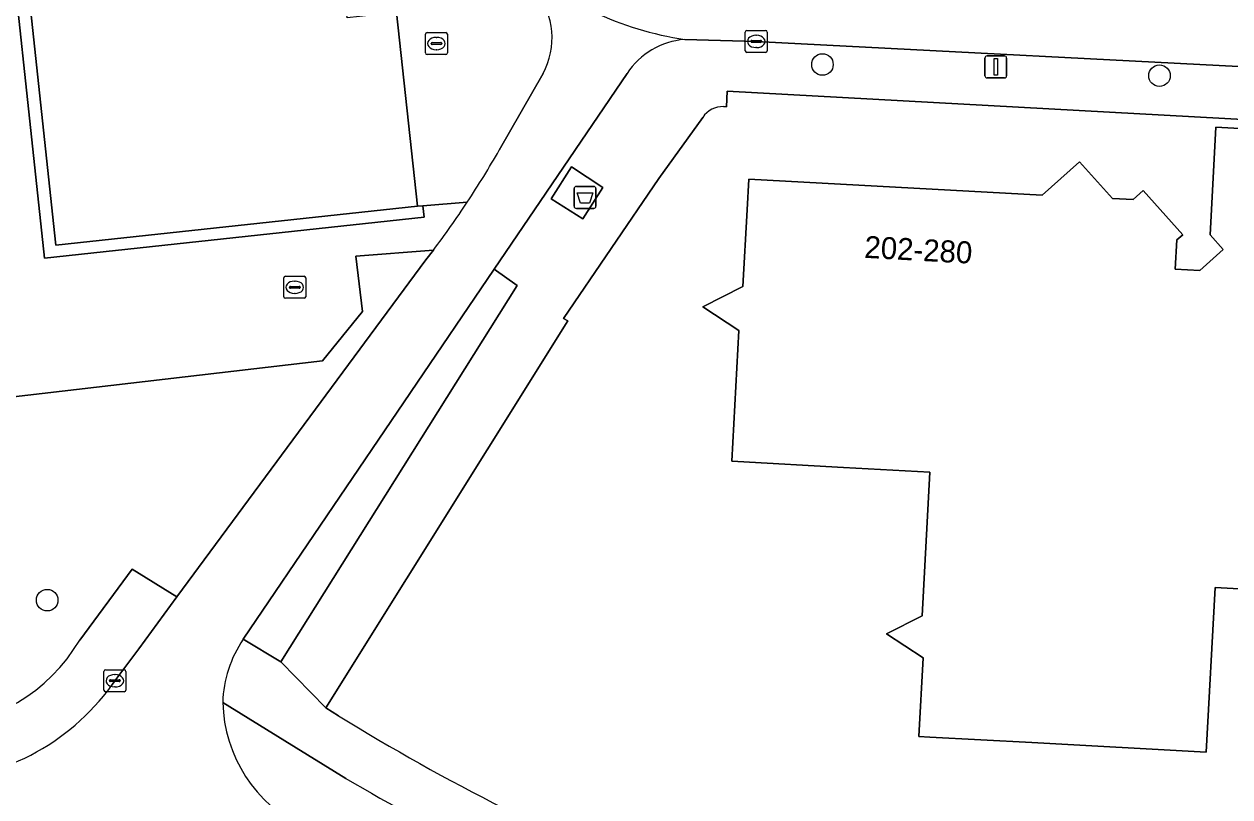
# Model space of a CAD drawing. Extents: x 161248 to 161848, y 384871 to 385383.
# Drawn here: x 161334.5 to 161389.3, y 384914.2 to 384949.3 of the extents above; entities that cross this region are included whole.
import ezdxf

# ---------------------------------------------------------------- set-up
doc = ezdxf.new("R2010")
doc.units = 0
for name, color, linetype in [('IMGEO_Afval_apart_plaats', 7, 'Continuous'), ('IMGEO_Berm_groen', 7, 'Continuous'), ('IMGEO_Boom', 7, 'Continuous'), ('IMGEO_Brandkraan', 7, 'Continuous'), ('IMGEO_Erf', 7, 'Continuous'), ('IMGEO_Fietspad_gesloten', 7, 'Continuous'), ('IMGEO_Groenvoorziening', 7, 'Continuous'), ('IMGEO_Haag', 7, 'Continuous'), ('IMGEO_Kolk', 7, 'Continuous'), ('IMGEO_Lichtmast', 7, 'Continuous'), ('IMGEO_Pand', 7, 'Continuous'), ('IMGEO_Pand_nummerreeks', 7, 'Continuous'), ('IMGEO_Rijbaan_lokaal_open', 7, 'Continuous'), ('IMGEO_Voetpad_gesloten', 7, 'Continuous'), ('IMGEO_Voetpad_open', 7, 'Continuous')]:
    doc.layers.add(name, color=color, linetype=linetype)

msp = doc.modelspace()

# ---------------------------------------------------------------- linework, layer by layer
at = {"layer": 'IMGEO_Afval_apart_plaats'}
for p, q in [((161359.468, 384941.031), (161359.468, 384941.831)), ((161359.468, 384941.831), (161359.468, 384941.031)), ((161359.568, 384941.931), (161360.358, 384941.931)), ((161360.358, 384941.931), (161359.568, 384941.931)), ((161360.458, 384941.831), (161360.458, 384941.031)), ((161360.458, 384941.031), (161360.458, 384941.831)), ((161360.358, 384940.931), (161359.568, 384940.931)), ((161359.568, 384940.931), (161360.358, 384940.931))]:
    msp.add_line(p, q, dxfattribs=at)
msp.add_lwpolyline([(161359.611, 384941.645), (161360.315, 384941.645), (161360.166, 384941.175), (161359.76, 384941.175), (161359.611, 384941.645)], dxfattribs=at)
for centre, start, end in [((161359.568, 384941.831), 90, 180), ((161359.568, 384941.831), 90, 180), ((161360.358, 384941.831), 0, 90), ((161360.358, 384941.831), 360, 90), ((161359.568, 384941.031), 180, 270), ((161359.568, 384941.031), 180, 270), ((161360.358, 384941.031), 270, 0), ((161360.358, 384941.031), 270, 0)]:
    msp.add_arc(centre, 0.1, start, end, dxfattribs=at)
at = {"layer": 'IMGEO_Berm_groen'}
msp.add_lwpolyline([(161349.092, 384915.021), (161346.317, 384916.731), (161343.493, 384918.478)], dxfattribs=at)
for centre, radius, start, end in [((161350.031, 384918.66), 6.541, 181.5976, 244.0484), ((161403.381, 385007.754), 107.456, 239.65384, 243.46089)]:
    msp.add_arc(centre, radius, start, end, dxfattribs=at)
at = {"layer": 'IMGEO_Boom'}
for centre in [(161370.755, 384947.473), (161386.077, 384946.965), (161335.512, 384923.126)]:
    msp.add_circle(centre, 0.489, dxfattribs=at)
at = {"layer": 'IMGEO_Brandkraan'}
for p, q in [((161352.707, 384948), (161352.707, 384948.852)), ((161352.782, 384948.926), (161353.634, 384948.926)), ((161352.966, 384948.42), (161352.966, 384948.432)), ((161353.009, 384948.469), (161353.407, 384948.469)), ((161353.195, 384948.706), (161353.22, 384948.706)), ((161353.45, 384948.432), (161353.45, 384948.42)), ((161353.708, 384948.852), (161353.708, 384948)), ((161353.634, 384947.926), (161352.782, 384947.926)), ((161353.404, 384948.383), (161353.006, 384948.383)), ((161353.218, 384948.146), (161353.193, 384948.146))]:
    msp.add_line(p, q, dxfattribs=at)
for points in [[(161352.707, 384948), (161352.707, 384948.852)], [(161352.782, 384948.926), (161353.634, 384948.926)], [(161353.708, 384948.852), (161353.708, 384948)], [(161353.634, 384947.926), (161352.782, 384947.926)]]:
    msp.add_lwpolyline(points, dxfattribs=at)
for centre, radius, start, end in [((161352.784, 384948.85), 0.0765, 91.552, 178.448), ((161352.784, 384948.85), 0.0765, 91.552, 178.448), ((161353.006, 384948.429), 0.0403, 85.8775, 175.7526), ((161353.003, 384948.419), 0.0366, 178.938, 274.7102), ((161353.407, 384948.426), 0.043, 264.8664, 352.4533), ((161353.411, 384948.431), 0.0386, 1.7309, 96.639), ((161353.632, 384948.85), 0.0765, 1.552, 88.448), ((161353.632, 384948.85), 0.0765, 1.552, 88.448), ((161352.784, 384948.002), 0.0765, 181.552, 268.448), ((161352.784, 384948.002), 0.0765, 181.552, 268.448), ((161353.632, 384948.002), 0.0765, 271.552, 358.448), ((161353.632, 384948.002), 0.0765, 271.552, 358.448)]:
    msp.add_arc(centre, radius, start, end, dxfattribs=at)
for centre, major_axis, ratio, start_param, end_param in [((161353.194, 384948.426), (-0.387, 0.002), 0.722429, 4.712389, 7.853982), ((161353.219, 384948.426), (-0.39, 0.002), 0.717154, 1.570796, 4.712389)]:
    msp.add_ellipse(centre, major_axis=major_axis, ratio=ratio, start_param=start_param, end_param=end_param, dxfattribs=at)
at = {"layer": 'IMGEO_Erf'}
for points in [[(161437.515, 384942.215), (161436.725, 384942.209), (161437.252, 384941.619), (161436.953, 384936.313), (161431.959, 384936.555), (161408.657, 384937.683), (161408.674, 384937.993), (161408.956, 384942.985), (161409.594, 384943.555), (161403.643, 384943.814), (161403.665, 384944.222), (161366.425, 384946.266), (161366.386, 384945.555), (161366.264, 384945.56)], [(161365.315, 384945.065), (161363.318, 384942.295), (161358.986, 384935.923), (161359.186, 384935.82), (161348.18, 384918.225), (161348.748, 384917.875)], [(161396.201, 384923.284), (161388.608, 384923.701), (161388.197, 384916.214), (161380.273, 384916.649), (161375.632, 384916.903), (161375.143, 384916.93), (161375.339, 384920.503), (161373.674, 384921.59), (161375.285, 384922.406), (161375.643, 384928.944), (161371.706, 384929.16), (161366.914, 384929.424), (161366.635, 384929.439), (161366.961, 384935.385), (161365.323, 384936.455), (161367.143, 384937.376), (161367.335, 384940.872), (161367.411, 384942.26), (161380.747, 384941.528), (161382.446, 384943.051), (161383.943, 384941.381), (161384.876, 384941.33), (161385.335, 384941.741), (161387.131, 384939.737), (161386.87, 384939.503), (161386.796, 384938.172), (161387.909, 384938.111), (161388.975, 384939.066), (161388.374, 384939.738), (161388.626, 384944.334), (161388.642, 384944.623), (161402.4, 384943.868)]]:
    msp.add_lwpolyline(points, dxfattribs=at)
for centre, radius, start, end in [((161366.217, 384944.493), 1.068, 87.4663, 147.6269), ((161402.791, 385005.617), 103.05, 238.37002, 247.93312)]:
    msp.add_arc(centre, radius, start, end, dxfattribs=at)
at = {"layer": 'IMGEO_Fietspad_gesloten'}
for points in [[(161344.427, 384921.346), (161355.831, 384938.171), (161361.875, 384947.059)], [(161358.055, 384947.061), (161356.066, 384943.583)], [(161353.067, 384939.032), (161352.732, 384938.592), (161341.413, 384923.282), (161339.671, 384920.911), (161338.589, 384919.464), (161338.457, 384919.26)]]:
    msp.add_lwpolyline(points, dxfattribs=at)
for centre, radius, start, end in [((161366.86, 384963.899), 15.474, 228.8729, 261.1978), ((161355.084, 384948.673), 3.38, 331.5226, 38.9105), ((161364.731, 384945.217), 3.399, 94.0321, 147.178), ((161318.363, 384965.194), 43.457, 326.5147, 330.1784), ((161318.717, 384964.883), 42.99, 323.0359, 326.601), ((161348.794, 384918.338), 5.302, 145.4371, 178.4859), ((161329.83, 384925.556), 10.68, 271.125, 323.8791), ((161350.031, 384918.66), 6.541, 181.5976, 244.0484)]:
    msp.add_arc(centre, radius, start, end, dxfattribs=at)
at = {"layer": 'IMGEO_Groenvoorziening'}
msp.add_lwpolyline([(161336.989, 384921.31), (161339.374, 384924.535), (161341.413, 384923.282), (161352.732, 384938.592), (161353.067, 384939.032), (161349.538, 384938.768), (161349.844, 384936.245), (161348.022, 384934.003), (161333.73, 384932.332), (161329.539, 384937.213), (161322.803, 385000)], dxfattribs=at)
msp.add_lwpolyline([(161355.831, 384938.171), (161344.427, 384921.346), (161346.132, 384920.317), (161356.875, 384937.434)], close=True, dxfattribs=at)
msp.add_arc((161330.018, 384925.42), 8.092, 272.132, 329.4792, dxfattribs=at)
at = {"layer": 'IMGEO_Haag'}
msp.add_lwpolyline([(161355.831, 384938.171), (161344.427, 384921.346), (161346.132, 384920.317), (161356.875, 384937.434)], close=True, dxfattribs=at)
at = {"layer": 'IMGEO_Kolk'}
for p, q in [((161367.245, 384948.098), (161367.245, 384948.95)), ((161367.32, 384949.024), (161368.172, 384949.024)), ((161368.246, 384948.95), (161368.246, 384948.098)), ((161367.504, 384948.518), (161367.504, 384948.53)), ((161367.942, 384948.481), (161367.544, 384948.481)), ((161367.547, 384948.567), (161367.945, 384948.567)), ((161367.733, 384948.804), (161367.758, 384948.804)), ((161367.988, 384948.53), (161367.988, 384948.518)), ((161368.172, 384948.024), (161367.32, 384948.024)), ((161367.756, 384948.244), (161367.731, 384948.244)), ((161346.267, 384936.92), (161346.267, 384937.772)), ((161346.342, 384937.846), (161347.194, 384937.846)), ((161346.755, 384937.626), (161346.78, 384937.626)), ((161347.268, 384937.772), (161347.268, 384936.92)), ((161346.526, 384937.34), (161346.526, 384937.352)), ((161346.964, 384937.303), (161346.566, 384937.303)), ((161346.569, 384937.389), (161346.967, 384937.389)), ((161346.778, 384937.066), (161346.753, 384937.066)), ((161347.01, 384937.352), (161347.01, 384937.34)), ((161347.194, 384936.846), (161346.342, 384936.846)), ((161338.088, 384919.038), (161338.088, 384919.89)), ((161338.163, 384919.964), (161339.015, 384919.964)), ((161339.089, 384919.89), (161339.089, 384919.038)), ((161338.347, 384919.458), (161338.347, 384919.47)), ((161338.785, 384919.421), (161338.387, 384919.421)), ((161338.39, 384919.507), (161338.788, 384919.507)), ((161338.576, 384919.744), (161338.601, 384919.744)), ((161338.831, 384919.47), (161338.831, 384919.458)), ((161339.015, 384918.964), (161338.163, 384918.964)), ((161338.599, 384919.184), (161338.574, 384919.184))]:
    msp.add_line(p, q, dxfattribs=at)
for points in [[(161367.245, 384948.098), (161367.245, 384948.95)], [(161367.32, 384949.024), (161368.172, 384949.024)], [(161368.246, 384948.95), (161368.246, 384948.098)], [(161368.172, 384948.024), (161367.32, 384948.024)], [(161346.267, 384936.92), (161346.267, 384937.772)], [(161346.342, 384937.846), (161347.194, 384937.846)], [(161347.268, 384937.772), (161347.268, 384936.92)], [(161347.194, 384936.846), (161346.342, 384936.846)], [(161338.088, 384919.038), (161338.088, 384919.89)], [(161338.163, 384919.964), (161339.015, 384919.964)], [(161339.089, 384919.89), (161339.089, 384919.038)], [(161339.015, 384918.964), (161338.163, 384918.964)]]:
    msp.add_lwpolyline(points, dxfattribs=at)
for centre, radius, start, end in [((161367.322, 384948.948), 0.0765, 91.552, 178.448), ((161367.322, 384948.948), 0.0765, 91.552, 178.448), ((161368.17, 384948.948), 0.0765, 1.552, 88.448), ((161368.17, 384948.948), 0.0765, 1.552, 88.448), ((161367.544, 384948.527), 0.0403, 85.8775, 175.7526), ((161367.541, 384948.517), 0.0366, 178.938, 274.7102), ((161367.945, 384948.524), 0.043, 264.8664, 352.4533), ((161367.949, 384948.529), 0.0386, 1.7309, 96.639), ((161367.322, 384948.1), 0.0765, 181.552, 268.448), ((161367.322, 384948.1), 0.0765, 181.552, 268.448), ((161368.17, 384948.1), 0.0765, 271.552, 358.448), ((161368.17, 384948.1), 0.0765, 271.552, 358.448), ((161346.344, 384937.77), 0.0765, 91.552, 178.448), ((161346.344, 384937.77), 0.0765, 91.552, 178.448), ((161347.192, 384937.77), 0.0765, 1.552, 88.448), ((161347.192, 384937.77), 0.0765, 1.552, 88.448), ((161346.344, 384936.922), 0.0765, 181.552, 268.448), ((161346.344, 384936.922), 0.0765, 181.552, 268.448), ((161346.566, 384937.349), 0.0403, 85.8775, 175.7526), ((161346.563, 384937.339), 0.0366, 178.938, 274.7102), ((161346.967, 384937.346), 0.043, 264.8664, 352.4533), ((161346.971, 384937.351), 0.0386, 1.7309, 96.639), ((161347.192, 384936.922), 0.0765, 271.552, 358.448), ((161347.192, 384936.922), 0.0765, 271.552, 358.448), ((161338.165, 384919.888), 0.0765, 91.552, 178.448), ((161338.165, 384919.888), 0.0765, 91.552, 178.448), ((161339.013, 384919.888), 0.0765, 1.552, 88.448), ((161339.013, 384919.888), 0.0765, 1.552, 88.448), ((161338.387, 384919.467), 0.0403, 85.8775, 175.7526), ((161338.384, 384919.457), 0.0366, 178.938, 274.7102), ((161338.788, 384919.464), 0.043, 264.8664, 352.4533), ((161338.792, 384919.469), 0.0386, 1.7309, 96.639), ((161338.165, 384919.04), 0.0765, 181.552, 268.448), ((161338.165, 384919.04), 0.0765, 181.552, 268.448), ((161339.013, 384919.04), 0.0765, 271.552, 358.448), ((161339.013, 384919.04), 0.0765, 271.552, 358.448)]:
    msp.add_arc(centre, radius, start, end, dxfattribs=at)
for centre, major_axis, ratio, start_param, end_param in [((161367.732, 384948.524), (-0.387, 0.002), 0.722429, 4.712389, 7.853982), ((161367.757, 384948.524), (-0.39, 0.002), 0.717154, 1.570796, 4.712389), ((161346.754, 384937.346), (-0.387, 0.002), 0.722429, 4.712389, 7.853982), ((161346.779, 384937.346), (-0.39, 0.002), 0.717154, 1.570796, 4.712389), ((161338.575, 384919.464), (-0.387, 0.002), 0.722429, 4.712389, 7.853982), ((161338.6, 384919.464), (-0.39, 0.002), 0.717154, 1.570796, 4.712389)]:
    msp.add_ellipse(centre, major_axis=major_axis, ratio=ratio, start_param=start_param, end_param=end_param, dxfattribs=at)
at = {"layer": 'IMGEO_Lichtmast'}
for p, q in [((161378.239, 384947.865), (161379.029, 384947.865)), ((161379.029, 384947.865), (161378.239, 384947.865)), ((161378.139, 384946.965), (161378.139, 384947.765)), ((161378.139, 384947.765), (161378.139, 384946.965)), ((161379.129, 384947.765), (161379.129, 384946.965)), ((161379.129, 384946.965), (161379.129, 384947.765)), ((161379.029, 384946.865), (161378.239, 384946.865)), ((161378.239, 384946.865), (161379.029, 384946.865))]:
    msp.add_line(p, q, dxfattribs=at)
msp.add_lwpolyline([(161378.559, 384947.74), (161378.709, 384947.74), (161378.709, 384946.99), (161378.559, 384946.99), (161378.559, 384947.74)], dxfattribs=at)
for centre, start, end in [((161378.239, 384947.765), 90, 180), ((161378.239, 384947.765), 90, 180), ((161379.029, 384947.765), 0, 90), ((161379.029, 384947.765), 360, 90), ((161378.239, 384946.965), 180, 270), ((161378.239, 384946.965), 180, 270), ((161379.029, 384946.965), 270, 0), ((161379.029, 384946.965), 270, 0)]:
    msp.add_arc(centre, 0.1, start, end, dxfattribs=at)
at = {"layer": 'IMGEO_Pand'}
msp.add_lwpolyline([(161349.099, 384971.364), (161346.806, 384971.118), (161346.282, 384975.989), (161347.495, 384976.119), (161347.464, 384976.414), (161332.09, 384974.761), (161335.907, 384939.267), (161352.34, 384941.034), (161351.394, 384949.836), (161349.145, 384949.594), (161348.631, 384954.373), (161349.881, 384954.507), (161349.815, 384955.119), (161348.591, 384954.987), (161348.072, 384959.82), (161348.677, 384959.885), (161348.309, 384963.303), (161347.699, 384963.238), (161346.913, 384970.539), (161349.162, 384970.781)], close=True, dxfattribs=at)
msp.add_lwpolyline([(161402.4, 384943.868), (161388.642, 384944.623), (161388.626, 384944.334), (161388.374, 384939.738), (161388.975, 384939.066), (161387.909, 384938.111), (161386.796, 384938.172), (161386.87, 384939.503), (161387.131, 384939.737), (161385.335, 384941.741), (161384.876, 384941.33), (161383.943, 384941.381), (161382.446, 384943.051), (161380.747, 384941.528), (161367.411, 384942.26), (161367.335, 384940.872), (161367.143, 384937.376), (161365.323, 384936.455), (161366.961, 384935.385), (161366.635, 384929.439), (161366.914, 384929.424), (161371.706, 384929.16), (161375.643, 384928.944), (161375.285, 384922.406), (161373.674, 384921.59), (161375.339, 384920.503), (161375.143, 384916.93), (161375.632, 384916.903), (161380.273, 384916.649), (161388.197, 384916.214), (161388.608, 384923.701), (161396.201, 384923.284)], dxfattribs=at)
at = {"layer": 'IMGEO_Rijbaan_lokaal_open'}
for points in [[(161326.219, 385023.721), (161335.826, 385024.754), (161335.778, 385025.258), (161326.818, 385024.285), (161326.594, 385026.253), (161319.802, 385024.058), (161320.382, 385022.568), (161322.803, 385000), (161329.539, 384937.213), (161333.73, 384932.332), (161348.022, 384934.003), (161349.844, 384936.245), (161349.538, 384938.768), (161353.067, 384939.032)], [(161354.608, 384941.218), (161352.588, 384941.054), (161352.645, 384940.528), (161335.385, 384938.672), (161333.36, 384957.504), (161332.965, 384957.461), (161331.628, 384969.898), (161332.002, 384969.938), (161331.017, 384979.097), (161330.667, 384979.059), (161329.341, 384991.388), (161329.661, 384991.422), (161328.734, 385000), (161328.683, 385000.47), (161328.371, 385000.44), (161327.034, 385012.879), (161327.381, 385012.916), (161326.219, 385023.721)], [(161364.492, 384948.607), (161367.746, 384948.524), (161392.878, 384947.213), (161402.342, 384946.764), (161409.808, 384946.409), (161436.678, 384945.133)]]:
    msp.add_lwpolyline(points, dxfattribs=at)
for centre, radius, start, end in [((161366.86, 384963.899), 15.474, 228.8729, 261.1978), ((161318.717, 384964.883), 42.99, 323.0359, 326.601)]:
    msp.add_arc(centre, radius, start, end, dxfattribs=at)
at = {"layer": 'IMGEO_Voetpad_gesloten'}
msp.add_lwpolyline([(161359.352, 384942.829), (161358.427, 384941.375), (161359.865, 384940.463), (161360.772, 384941.881)], close=True, dxfattribs=at)
at = {"layer": 'IMGEO_Voetpad_open'}
for points in [[(161343.203, 385026.481), (161343.3, 385025.559), (161343.862, 385025.619), (161345.069, 385014.386), (161345.626, 385014.446), (161346.272, 385008.441), (161345.12, 385008.375), (161345.635, 385003.548), (161346.825, 384992.221), (161347.327, 384987.554), (161347.916, 384982.064), (161347.976, 384981.513), (161349.099, 384971.364), (161349.162, 384970.781), (161351.394, 384949.836), (161352.34, 384941.034), (161352.588, 384941.054), (161354.608, 384941.218)], [(161333.36, 384957.504), (161335.385, 384938.672), (161352.645, 384940.528), (161352.588, 384941.054), (161352.34, 384941.034), (161335.907, 384939.267), (161332.09, 384974.761)], [(161436.678, 384945.133), (161409.808, 384946.409), (161402.342, 384946.764), (161392.878, 384947.213), (161367.746, 384948.524), (161364.492, 384948.607)], [(161361.875, 384947.059), (161355.831, 384938.171), (161356.875, 384937.434), (161346.132, 384920.317), (161348.18, 384918.225), (161359.186, 384935.82), (161358.986, 384935.923), (161363.318, 384942.295), (161365.315, 384945.065)], [(161356.066, 384943.583), (161358.055, 384947.061)], [(161366.264, 384945.56), (161366.386, 384945.555), (161366.425, 384946.266), (161403.665, 384944.222), (161403.643, 384943.814), (161409.594, 384943.555), (161415.542, 384943.219), (161416.074, 384942.623), (161416.752, 384943.229), (161422.553, 384942.902), (161423.078, 384942.313), (161423.695, 384942.864), (161429.486, 384942.538), (161429.999, 384941.963), (161430.658, 384942.551), (161436.725, 384942.209), (161437.515, 384942.215)], [(161338.457, 384919.26), (161338.589, 384919.464), (161339.671, 384920.911), (161341.413, 384923.282), (161339.374, 384924.535), (161336.989, 384921.31)], [(161348.748, 384917.875), (161348.18, 384918.225), (161346.132, 384920.317), (161344.427, 384921.346)], [(161343.493, 384918.478), (161346.317, 384916.731), (161349.092, 384915.021)]]:
    msp.add_lwpolyline(points, dxfattribs=at)
msp.add_lwpolyline([(161359.352, 384942.829), (161360.772, 384941.881), (161359.865, 384940.463), (161358.427, 384941.375)], close=True, dxfattribs=at)
for centre, radius, start, end in [((161355.084, 384948.673), 3.38, 331.5226, 38.9105), ((161364.731, 384945.217), 3.399, 94.0321, 147.178), ((161366.217, 384944.493), 1.068, 87.4663, 147.6269), ((161318.363, 384965.194), 43.457, 326.5147, 330.1784), ((161330.018, 384925.42), 8.092, 272.132, 329.4792), ((161348.794, 384918.338), 5.302, 145.4371, 178.4859), ((161329.83, 384925.556), 10.68, 271.125, 323.8791), ((161402.791, 385005.617), 103.05, 238.37002, 247.93312), ((161403.381, 385007.754), 107.456, 239.65384, 243.46089)]:
    msp.add_arc(centre, radius, start, end, dxfattribs=at)

# ---------------------------------------------------------------- texts
at = {"layer": 'IMGEO_Pand_nummerreeks'}
msp.add_text('202-280', height=1, rotation=356.8582, dxfattribs=at).set_placement((161372.641, 384938.688))

doc.saveas('drawing.dxf')
